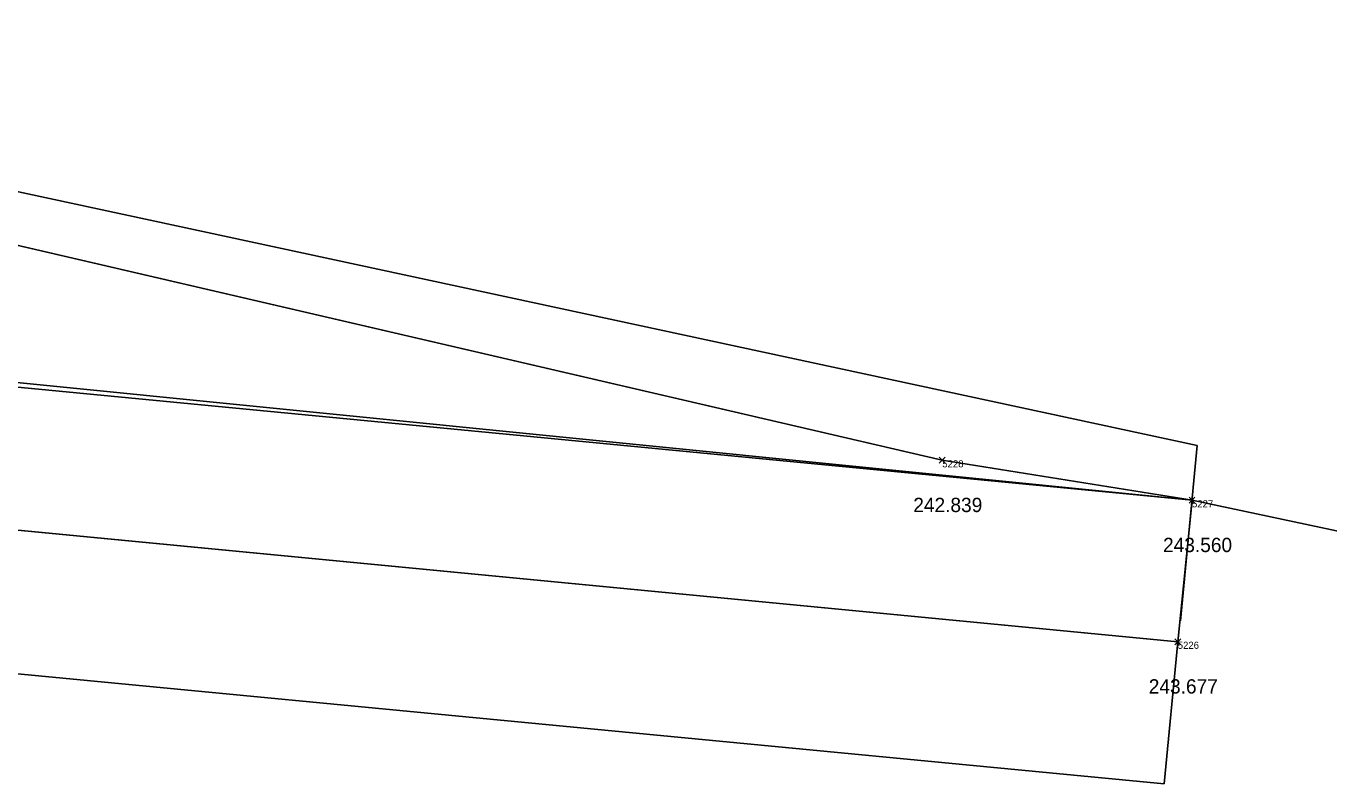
# Model space of a CAD drawing. Extents: x -809973 to -809318, y -1011363 to -1010505.
# Drawn here: x -809852.68 to -809843.56, y -1010878 to -1010872.69 of the extents above; entities that cross this region are included whole.
import ezdxf

# ---------------------------------------------------------------- set-up
doc = ezdxf.new("R2010")
doc.units = 0
for name, color, linetype in [('18b - zaměření - čísla bodů', 7, 'Continuous'), ('18c - zaměření - výšky', 7, 'Continuous'), ('SO_02', 7, 'Continuous'), ('stav_stav', 7, 'Continuous')]:
    doc.layers.add(name, color=color, linetype=linetype)

# ---------------------------------------------------------------- blocks, each defined once
blk = doc.blocks.new('POINT_DISPLAY')
for p, q in [((-0.021, -0.021), (0.021, 0.021)), ((-0.021, 0.021), (0.021, -0.021))]:
    blk.add_line(p, q)

msp = doc.modelspace()

# ---------------------------------------------------------------- linework, layer by layer
at = {"layer": 'SO_02'}
for p, q in [((-809858.1238, -1010872.6911), (-809844.4813, -1010875.6277)), ((-809857.52, -1010874.709), (-809844.518, -1010876.01)), ((-809857.555, -1010874.757), (-809844.518, -1010876.01)), ((-809844.4813, -1010875.6277), (-809844.5991, -1010876.8538)), ((-809844.618, -1010877), (-809857.4078, -1010875.7726)), ((-809844.618, -1010877), (-809856.883, -1010875.823)), ((-809844.518, -1010876.01), (-809844.618, -1010877)), ((-809844.518, -1010876.01), (-809844.618, -1010877)), ((-809844.7135, -1010877.9954), (-809857.2554, -1010876.7919)), ((-809844.618, -1010877), (-809844.7135, -1010877.9954))]:
    msp.add_line(p, q, dxfattribs=at)
msp.add_lwpolyline([(-809844.518, -1010876.01), (-809846.267, -1010875.73), (-809858.004, -1010873.004), (-809858.054, -1010872.755), (-809858.062, -1010873.154)], dxfattribs=at)
at = {"layer": 'stav_stav'}
for p, q in [((-809846.267, -1010875.73), (-809858.004, -1010873.004)), ((-809857.52, -1010874.709), (-809844.518, -1010876.01)), ((-809857.555, -1010874.757), (-809844.518, -1010876.01)), ((-809844.518, -1010876.01), (-809846.267, -1010875.73)), ((-809844.618, -1010877), (-809856.883, -1010875.823)), ((-809844.618, -1010877), (-809856.883, -1010875.823)), ((-809844.518, -1010876.01), (-809844.618, -1010877)), ((-809844.518, -1010876.01), (-809844.618, -1010877)), ((-809839.978, -1010876.967), (-809844.518, -1010876.01))]:
    msp.add_line(p, q, dxfattribs=at)

# ---------------------------------------------------------------- block references
at = {"layer": '18b - zaměření - čísla bodů'}
for p in [(-809846.267, -1010875.73), (-809844.518, -1010876.01), (-809844.618, -1010877)]:
    msp.add_blockref('POINT_DISPLAY', p, dxfattribs=at)

# ---------------------------------------------------------------- texts
for s, p in [('5228', (-809846.267, -1010875.78)), ('5227', (-809844.518, -1010876.06)), ('5226', (-809844.618, -1010877.05))]:
    msp.add_text(s, height=0.05, dxfattribs=at).set_placement(p)
at = {"layer": '18c - zaměření - výšky'}
for s, p in [('242.839', (-809846.4699, -1010876.0927)), ('243.560', (-809844.7207, -1010876.3727)), ('243.677', (-809844.8207, -1010877.3627))]:
    msp.add_text(s, height=0.1, dxfattribs=at).set_placement(p)

doc.saveas('drawing.dxf')
